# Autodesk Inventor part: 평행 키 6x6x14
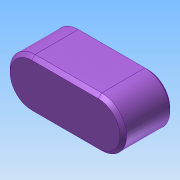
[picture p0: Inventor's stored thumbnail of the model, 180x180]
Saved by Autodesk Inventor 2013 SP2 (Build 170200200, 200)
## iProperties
Created: 2025-08
Part Number: 평행 키 6x6x14
Material: Generic
Document SubType Name: Modeling
Designer: i
Density: 1 g/cm^3
Author: i
변환 표준: STEP AP214IS
전처리기: Build: 200, Release: 2013 SP2 Update 6 - Date: Thu 07/17/2014
전송 단위: 밀리미터
불확실성: 0.01
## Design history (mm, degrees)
node "평행 키 6x6x141"
body "Solid1"
node "기준1"
